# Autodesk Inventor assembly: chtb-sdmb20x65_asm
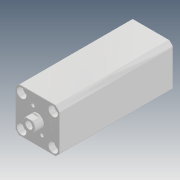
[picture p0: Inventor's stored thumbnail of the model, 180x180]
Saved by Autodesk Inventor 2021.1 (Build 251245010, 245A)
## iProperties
Company: Microsoft
Created: 2018-05
Part Number: chtb-sdmb20x65_asm
Description: STEP AP214
Document SubType Name: Assembly
Designer: user
Title: chtb-sdmb20x65_asm.STEP
Author: Windows
Revision Number: ÈÎºÎ
Sending System: SolidWorks 2015
Preprocessor: SwSTEP 2.0
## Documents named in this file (4)
- D:\Vault_2016\Projekty\Clamptek\Hydraulic\CHTB\CHTB-20\Inventor\CHTB-SDMB20x65\chtb-sdmb20x65_asm.iam
- D:\Vault_2016\Projekty\Clamptek\Hydraulic\CHTB\CHTB-20\Inventor\CHTB-SDMB20x65\CHTB-SDMB20X65NBT.ipt
- D:\Vault_2016\Projekty\Clamptek\Hydraulic\CHTB\CHTB-20\Inventor\CHTB-SDMB20x65\CHTB-SDMB20X65NHSG.ipt
- D:\Vault_2016\Projekty\Clamptek\Hydraulic\CHTB\CHTB-20\Inventor\CHTB-SDMB20x65\QG_3.ipt
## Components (3 placed, 3 different names)
1. CHTB-SDMB20X65NBT_1
2. CHTB-SDMB20X65NHSG_2
3. QG_3_3
